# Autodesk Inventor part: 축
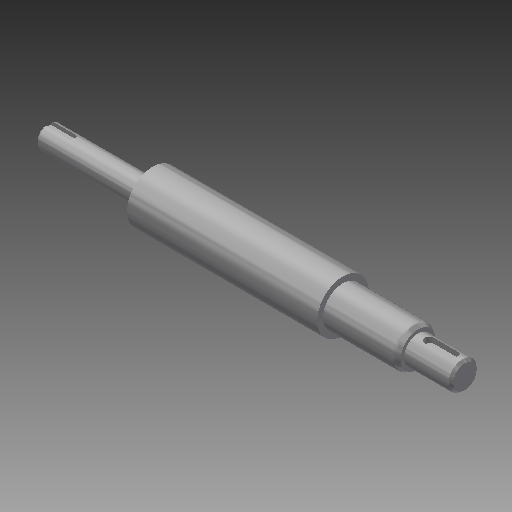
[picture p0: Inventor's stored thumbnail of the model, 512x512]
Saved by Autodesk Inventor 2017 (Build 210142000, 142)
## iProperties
Created: 2016-05
Part Number: 축
Document SubType Name: Modeling
Designer: mduedu
Density: 7.86 g/cm^3
Material: 강철, 연강
Appearance: 강철
Author: mduedu
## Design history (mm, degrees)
sketch "스케치1"
  geometry: L1 (-44, 11)-(-44, 5); L2 (37, 11)-(37, 8.5); L3 (-89, 0)-(89, 0); L4 (-44, 11)-(37, 11); L5 (37, 11)-(37, 8.5); L6 (-44, 11)-(-44, 5); L7 (-44, 5)-(-89, 5); L8 (-89, 5)-(-89, 0); L9 (37, 8.5)-(69, 8.5); L10 (89, 6)-(89, 0); L11 (69, 8.5)-(69, 6); L12 (69, 6)-(89, 6); 1 further point
  constraints: 24 end point, 9 perpendicular, 2 midpoint, 1 horizontal
  dimensions: "d0" = 22 diameter of L4 L3; "d1" = 10 diameter of L7 L3; "d2" = 45 distance between parallel lines of L8 L1; "d3" = 52 distance between parallel lines of L10 L2; "d4" = 12 diameter of L12 L3; "d5" = 20 distance between parallel lines of L10 L11; "d29" = 81 distance of L1.start L2.start; "d37" = 17 diameter of L9 L3
revolve "회전1" stored, may be unused: angle "d6" = 90 deg
chamfer "모따기2" distance "d32" = 1; stored, may be unused: second distance "d33" = 2, angle "d34" = 45 deg
node "작업 평면4"
sketch "스케치4"
  geometry: L1 (-5, 2)-(5, 2); L2 (5, -2)-(-5, -2); L3 (-10, -5)-(-10, 5) reference; A1 r 2 centre (5, 0) between (5, -2) and (5, 2); A2 r 2 centre (-5, 0) between (-5, 2) and (-5, -2); 1 further point
  constraints: 4 end point, 4 point on circle, 4 tangent, 2 centre point, 1 horizontal, 1 horizontal alignment, 1 parallel
  dimensions: "d20" = 4 distance between parallel lines of L2 L1; "d21" = 14 dimension on A1 A2; "d35" = 3 distance edge to line of A2 L3
extrude "돌출3" cut sketch "스케치4" distance "d23" = 2.5; taper "d24" = 0 deg
node "작업 평면5"
sketch "스케치5"
  geometry: L1 (22.5, 1.5)-(12, 1.5); L2 (12, -1.5)-(22.5, -1.5); L3 (22.5, 4)-(22.5, -4) reference; A1 r 1.5 centre (12, 0) between (12, 1.5) and (12, -1.5); 3 further points
  constraints: 4 end point, 2 horizontal alignment, 2 point on circle, 2 point on line, 2 tangent, 1 centre point, 1 coincident, 1 horizontal, 1 midpoint
  dimensions: "d25" = 3 distance between parallel lines of L2 L1; "d36" = 12 dimension on A1 L3
extrude "돌출4" cut sketch "스케치5" distance "d27" = 1.8; taper "d28" = 0 deg
chamfer "모따기3" distance "d38" = 1.82; stored, may be unused: second distance "d39" = 2, angle "d40" = 30 deg
fillet "모깎기1" dims "d41" = 2
node "솔리드1"
